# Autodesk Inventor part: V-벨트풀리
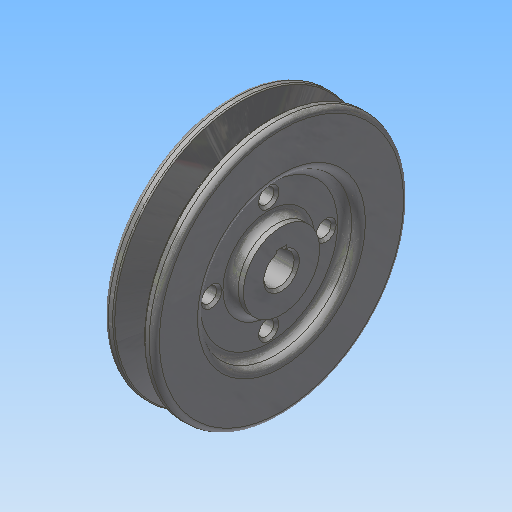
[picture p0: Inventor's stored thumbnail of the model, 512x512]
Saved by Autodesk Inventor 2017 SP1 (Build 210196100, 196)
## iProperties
Created: 2015-09
Part Number: V-벨트풀리
Material: 강철, 연강
Document SubType Name: Modeling
Designer: mduedu
Density: 1 g/cm^3
Appearance: 강철
Author: mduedu
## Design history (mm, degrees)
sketch "스케치1"
  geometry: L1 (-10, 0)-(10, 0); L2 (-10, 0)-(-10, 50); L3 (-10, 50)-(-5.976, 50); L4 (-5.976, 50)-(-2.154, 37.5); L5 (-2.154, 37.5)-(2.154, 37.5); L6 (2.154, 37.5)-(5.976, 50); L7 (5.976, 50)-(10, 50); L8 (10, 50)-(10, 0); L9 (0, 0)-(0, 37.5); L10 (-10, 45.5)-(10, 45.5); 3 further points
  constraints: 20 end point, 6 point on line, 3 perpendicular, 2 midpoint, 2 parallel, 2 symmetric about line, 1 coincident, 1 collinear, 1 equal length, 1 horizontal, 1 vertical, 1 vertical alignment
  dimensions: "d0" = 20 distance between parallel lines of L8 L2; "d2" = 100 diameter of L3 L1; "d5" = 8 distance between parallel lines of L5 L10; "d6" = 9.2 distance of point (4.6, 45.5) point (-4.6, 45.5); "d7" = 34 deg angle of L6 L4; "d40" = 4.5 distance between parallel lines of L10 L3
revolve "회전1" sketch "스케치1" stored, may be unused: angle "d8" = 90 deg
sketch "스케치2"
  geometry: C1 r 15 at (0, 0); C2 r 30 at (0, 0); 1 further point
  constraints: 2 centre point, 2 coincident
  dimensions: "d9" = 30 diameter of C1; "d41" = 60 diameter of C2
extrude "돌출5" cut sketch "스케치2" distance "d42" = 5; taper "d43" = 0 deg
hole "구멍2" diameter "d46" = 12; stored, may be unused: countersink angle "d50" = 90 deg, drill point angle "d52" = 118 deg; dims "d44" = 10, "d45" = 10, "d47" = 6, "d48" = 4, "d49" = 2, "d51" = 8
sketch "스케치8"
  geometry: L1 (-2, 5.657)-(2, 5.657); L2 (2, 5.657)-(2, 7.8); L3 (2, 7.8)-(-2, 7.8); L4 (-2, 7.8)-(-2, 5.657); A1 r 6 centre (0, 0) between (-2, 5.657) and (2, 5.657) reference; 1 further point
  constraints: 8 end point, 2 parallel, 2 point on circle, 1 horizontal, 1 perpendicular
  dimensions: "d53" = 4 distance of L2.end L3.end; "d55" = 13.8 dimension on A1 L3
extrude "돌출6" cut sketch "스케치8" stored distance "d56" = 5; taper "d57" = 0 deg
sketch "스케치9"
  geometry: C1 r 3 at (0, 22.5); 1 further point
  constraints: 1 centre point, 1 vertical alignment
  dimensions: "d61" = 6 diameter of C1; "d62" = 22.5 distance of C1.centre point (0, 0)
extrude "돌출7" cut sketch "스케치9" stored distance "d63" = 5; taper "d64" = 0 deg
chamfer "모따기3" distance "d65" = 1; stored, may be unused: second distance "d66" = 2, angle "d67" = 45 deg
fillet "모깎기5" dims "d71" = 2, "d72" = 1, "d73" = 0.5
fillet "모깎기6" dims "d74" = 3
fillet "모깎기7" dims "d75" = 3
fillet "모깎기8" dims "d76" = 3
chamfer "모따기4" distance "d82" = 1; stored, may be unused: second distance "d83" = 2, angle "d84" = 45 deg
node "솔리드1"
mirror "대칭2"
pattern_circular "원형 패턴1" dims "d69" = 360 deg
